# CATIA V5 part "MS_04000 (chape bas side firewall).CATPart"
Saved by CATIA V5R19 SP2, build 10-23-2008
Part number: MS_04005 (Low Side Firewall Bracket)
Bounding box of the stored display mesh (mm): x -1146.869 to 0, y -234.325 to 0, z -93.973 to 0
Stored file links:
  D:\EPSA\GIT\ELIZ-2022\01 - Maquette CATIA\MS_Miscellanous_Finish_Assembly\MS_A0400 (Firewall)\MS_04000 (chape bas side firewall).CATPart
  D:\EPSA\GIT\ELIZ-2022\01 - Maquette CATIA\MS_Miscellanous_Finish_Assembly\MS_A0400 (Firewall)\MS_A0400 (FireWall).CATProduct
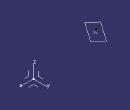
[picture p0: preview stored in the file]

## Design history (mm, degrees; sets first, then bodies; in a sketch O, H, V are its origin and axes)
AxisSystem1: origin (0, 0, 0), X (1, 0, 0), Y (0, 1, 0), Z (0, 0, 1)
Set1
  Point1: type OnCurve, Support DatumCurve1, Length 489.226
  Plane1: type Normal, Curve DatumCurve1, RefPoint Point1
  Sketch1 on Plane1, origin (-1142.8705, -200.5753, -87.9446), H (0.1729, -0.9849, 0), V (-0.0744, -0.0131, 0.9971)
    circle A1 centre (34.3462, -6.0462) radius 14
    point P1 (34.3462, -6.0462)
    reference projected point E1 (34.3462, -6.0462) from Point1
    radius A1 = 14
    coincidence: P1 E1
Set2
  DatumCurve1: linked copy from another document
  Plane2: linked copy from another document
  DatumSurface1 to DatumSurface3: linked copy from another document
Body1 (main body)
  Pad1: profile Sketch1, direction (-0.9821, -0.1724, -0.0756), length 30, opposite side length 30
  Point2: type OnSurface, Support face of Pad1 from Sketch1.A1, Length 10.962, Direction (-0.0367, 0.9244, -0.3797)
  Plane3: type Tangent, Support DatumSurface1, RefPoint Point2
  Line1: type PtDir, RefPoint Point2, Direction DatumCurve1, Start -25, End 23
Body2
  Sketch2 on face of DatumSurface3, origin (3.8523, -19.9899, -4.4703), H (-0.9819, -0.1892, 0), V (0.0406, -0.2106, 0.9767)
    reference intersected line E1 through (1160.1769, -90.0399) direction (0.0774, 0.997) from Plane1
    arc A1 centre (1162.3034, -62.6394) radius 7 from (1162.8451, -55.6603) to (1155.3244, -62.0977) ccw
    point P3 (1162.3034, -62.6394)
    point P4 (1162.8451, -55.6603)
    point P5 (1155.3244, -62.0977)
    line L1 (1155.3244, -62.0977) -> (1153.3126, -88.0198)
    point P6 (1153.3126, -88.0198)
    line L2 (1153.3126, -88.0198) -> (1160.2917, -88.5614)
    point P7 (1160.2917, -88.5614)
    reference intersected line E2 (1190.2017, -90.8827) -> (1130.3816, -86.2401) from face of Pad1 from Sketch1.A1
    circle A2 centre (1162.3034, -62.6394) radius 1.7
    point P10 (1160.2917, -88.5614)
    point P11 (1167.2707, -89.103)
    line L3 (1167.2707, -89.103) -> (1160.2917, -88.5614)
    point P12 (1169.2824, -63.181)
    line L4 (1169.2824, -63.181) -> (1167.2707, -89.103)
    point P13 (1162.8451, -55.6603)
    arc A3 centre (1162.3034, -62.6394) radius 7 from (1162.8451, -55.6603) to (1169.2824, -63.181) cw
    radius A1 = 7
    length L1 = 26
    radius A2 = 1.7
    coincidence: P3 E1, P4 E1, P7 E1, L2 E2, P4 P13, P7 P10
    tangency: L1 A1
    perpendicularity: L2 L1
    symmetry: P7 P10 E1, P6 P11 E1, L2 L3 E1, P5 P12 E1, L1 L4 E1, P4 P13 E1, A1 A3 E1
  Pad2: profile Sketch2, direction (0.1848, -0.9591, -0.2145), length 1.5
  Sketch3 on end face of Pad2, origin (4.1295, -21.4285, -4.792), H (0.9819, 0.1892, 0), V (0.0406, -0.2106, 0.9767)
    intersected line E1 (-1130.8694, -79.9543) -> (-1190.6896, -84.5968) from face of Pad1 from Sketch1.A1
    intersected line E2 (-1129.8938, -92.526) -> (-1189.7139, -97.1685) from face of Pad1 from Sketch1.A1
    point P3 (-1129.8938, -92.526)
    line L1 (-1190.6896, -84.5968) -> (-1189.7139, -97.1685)
    line L2 (-1130.8694, -79.9543) -> (-1129.8938, -92.526)
    point P5 (-1129.8938, -92.526)
    perpendicularity: L1 E1
    parallelism: L2 L1
    coincidence: P3 P5
  Pocket1: profile Sketch3, direction (-0.1848, 0.9591, 0.2145), up to start face of Pad2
